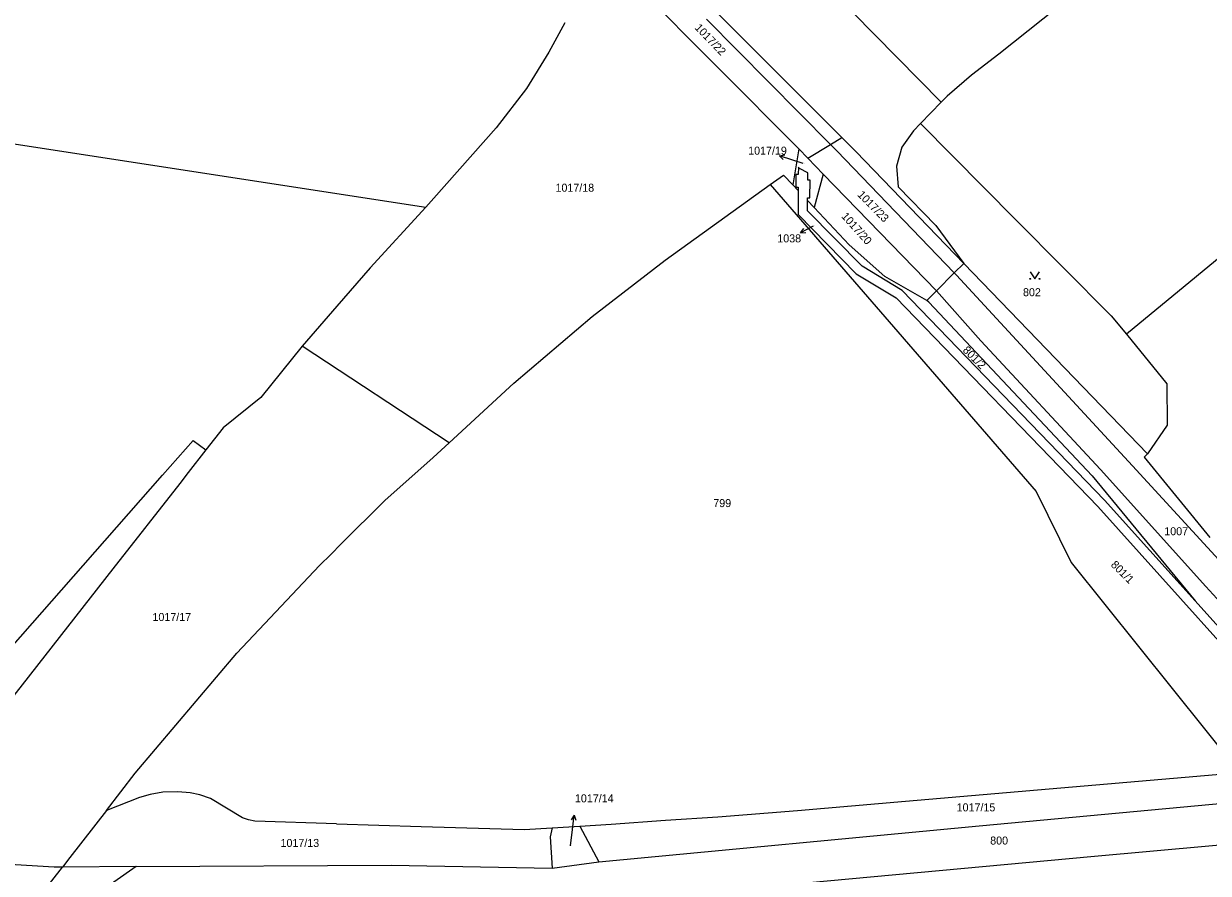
# Model space of a CAD drawing. Extents: x -738131 to -734179, y -1033447 to -1030078.
# Drawn here: x -736626.5 to -736374.8, y -1031869.7 to -1031689.1 of the extents above; entities that cross this region are included whole.
import ezdxf

# ---------------------------------------------------------------- set-up
doc = ezdxf.new("R2010")
doc.units = 0
for name, color, linetype in [('Vrstva 1', 7, 'Continuous'), ('Vrstva 2', 7, 'Continuous'), ('Vrstva 3', 7, 'Continuous'), ('Vrstva 4', 7, 'Continuous'), ('Vrstva 7', 7, 'Continuous')]:
    doc.layers.add(name, color=color, linetype=linetype)

msp = doc.modelspace()

# ---------------------------------------------------------------- linework, layer by layer
at = {"layer": 'Vrstva 1'}
for points in [[(-736431.56, -1031705.78), (-736478.56, -1031658.03)], [(-736496.26, -1031681.05), (-736461.83, -1031715.71)], [(-736403.74, -1031683.08), (-736419.34, -1031695.6)], [(-736452.7, -1031713.28), (-736480.2, -1031685.76)], [(-736511.58, -1031688.94), (-736514.98, -1031695.17)], [(-736514.98, -1031695.17), (-736519.67, -1031702.88)], [(-736419.34, -1031695.6), (-736425.13, -1031700.05)], [(-736317.82, -1031693.78), (-736392.24, -1031755.11)], [(-736736.47, -1031698.03), (-736541.12, -1031728.09)], [(-736425.13, -1031700.05), (-736430.29, -1031704.47)], [(-736519.67, -1031702.88), (-736526.15, -1031711.23)], [(-736430.29, -1031704.47), (-736431.56, -1031705.78)], [(-736431.56, -1031705.78), (-736435.97, -1031710.31)], [(-736435.97, -1031710.31), (-736437.48, -1031711.86)], [(-736435.97, -1031710.31), (-736415.73, -1031730.77)], [(-736526.15, -1031711.23), (-736539.38, -1031726.19)], [(-736437.48, -1031711.86), (-736439.92, -1031715.32)], [(-736461.83, -1031715.71), (-736463.09, -1031723.35)], [(-736459.92, -1031717.68), (-736461.83, -1031715.71)], [(-736459.92, -1031717.68), (-736455.11, -1031714.75)], [(-736455.11, -1031714.75), (-736452.7, -1031713.28)], [(-736449.65, -1031716.33), (-736452.7, -1031713.28)], [(-736439.92, -1031715.32), (-736441.07, -1031719.39)], [(-736456.65, -1031721.07), (-736459.92, -1031717.68)], [(-736426.79, -1031740.06), (-736449.65, -1031716.33)], [(-736461.92, -1031719.59), (-736461.94, -1031721.11)], [(-736461.68, -1031719.84), (-736461.92, -1031719.59)], [(-736459.93, -1031720.79), (-736461.68, -1031719.84)], [(-736459.95, -1031722.36), (-736459.93, -1031720.79)], [(-736441.07, -1031719.39), (-736440.71, -1031723.79)], [(-736490.24, -1031739.37), (-736467.89, -1031723.29)], [(-736467.89, -1031723.29), (-736465.07, -1031721.26)], [(-736467.89, -1031723.29), (-736411.42, -1031788.53)], [(-736463.09, -1031723.35), (-736465.07, -1031721.26)], [(-736462.44, -1031721.11), (-736462.46, -1031723.8)], [(-736461.94, -1031721.11), (-736462.44, -1031721.11)], [(-736459.45, -1031722.36), (-736459.95, -1031722.36)], [(-736459.48, -1031726.13), (-736459.45, -1031722.36)], [(-736456.65, -1031721.07), (-736458.59, -1031728.13)], [(-736432.58, -1031745.87), (-736456.65, -1031721.07)], [(-736461.96, -1031724.55), (-736463.09, -1031723.35)], [(-736462.46, -1031723.8), (-736461.96, -1031723.81)], [(-736461.96, -1031724.55), (-736462, -1031729.68)], [(-736461.96, -1031723.81), (-736461.96, -1031724.55)], [(-736440.71, -1031723.79), (-736432.72, -1031732.01)], [(-736541.12, -1031728.09), (-736552.89, -1031740.95)], [(-736539.38, -1031726.19), (-736541.12, -1031728.09)], [(-736460, -1031728.87), (-736459.98, -1031726.65)], [(-736459.98, -1031726.65), (-736459.98, -1031726.12)], [(-736459.98, -1031726.12), (-736459.48, -1031726.13)], [(-736458.59, -1031728.13), (-736459.98, -1031726.65)], [(-736451.11, -1031736.06), (-736458.59, -1031728.13)], [(-736462, -1031729.68), (-736449.65, -1031742.22)], [(-736448.4, -1031740.64), (-736460, -1031728.87)], [(-736415.73, -1031730.77), (-736395.45, -1031751.19)], [(-736432.72, -1031732.01), (-736426.79, -1031740.06)], [(-736443.59, -1031742.79), (-736451.11, -1031736.06)], [(-736552.89, -1031740.95), (-736560.01, -1031749.1)], [(-736505.76, -1031751.34), (-736490.24, -1031739.37)], [(-736439.91, -1031745.77), (-736448.4, -1031740.64)], [(-736428.8, -1031742.07), (-736426.79, -1031740.06)], [(-736426.79, -1031740.06), (-736387.78, -1031780.54)], [(-736449.65, -1031742.22), (-736441.16, -1031747.35)], [(-736434.66, -1031747.91), (-736443.59, -1031742.79)], [(-736432.58, -1031745.87), (-736428.8, -1031742.07)], [(-736396.85, -1031790.37), (-736439.91, -1031745.77)], [(-736432.58, -1031745.87), (-736434.66, -1031747.91)], [(-736441.16, -1031747.35), (-736398.32, -1031791.71)], [(-736434.2, -1031748.27), (-736434.66, -1031747.91)], [(-736399.5, -1031785.22), (-736434.2, -1031748.27)], [(-736560.01, -1031749.1), (-736567.35, -1031757.66)], [(-736522.38, -1031765.51), (-736505.76, -1031751.34)], [(-736395.45, -1031751.19), (-736392.24, -1031755.11)], [(-736392.24, -1031755.11), (-736383.64, -1031765.6)], [(-736567.35, -1031757.66), (-736576.16, -1031768.52)], [(-736536.1, -1031778.14), (-736567.35, -1031757.66)], [(-736536.1, -1031778.14), (-736522.38, -1031765.51)], [(-736383.64, -1031765.6), (-736383.56, -1031774.39)], [(-736576.16, -1031768.52), (-736584.15, -1031775.01)], [(-736584.15, -1031775.01), (-736587.82, -1031779.69)], [(-736383.56, -1031774.39), (-736387.78, -1031780.54)], [(-736597.05, -1031785.07), (-736590.56, -1031777.69)], [(-736590.56, -1031777.69), (-736587.82, -1031779.69)], [(-736536.1, -1031778.14), (-736539.53, -1031781.3)], [(-736587.82, -1031779.69), (-736591.56, -1031784.47)], [(-736388.45, -1031781.21), (-736387.78, -1031780.54)], [(-736388.45, -1031781.21), (-736374.52, -1031798.29)], [(-736539.53, -1031781.3), (-736549.79, -1031790.4)], [(-736613.89, -1031804.22), (-736597.05, -1031785.07)], [(-736591.56, -1031784.47), (-736593.37, -1031786.79)], [(-736399.5, -1031785.22), (-736377.64, -1031811.73)], [(-736593.37, -1031786.79), (-736607.57, -1031804.92)], [(-736411.42, -1031788.53), (-736403.94, -1031803.64)], [(-736549.79, -1031790.4), (-736559.12, -1031799.71)], [(-736377.64, -1031811.73), (-736396.85, -1031790.37)], [(-736398.32, -1031791.71), (-736355, -1031839.89)], [(-736559.12, -1031799.71), (-736561.22, -1031801.8)], [(-736561.22, -1031801.8), (-736563.69, -1031804.27)], [(-736403.94, -1031803.64), (-736368.19, -1031848.25)], [(-736607.57, -1031804.92), (-736654.08, -1031864.32)], [(-736629.29, -1031821.73), (-736613.89, -1031804.22)], [(-736563.69, -1031804.27), (-736574.17, -1031815.37)], [(-736353.52, -1031838.55), (-736377.64, -1031811.73)], [(-736581.28, -1031822.91), (-736574.17, -1031815.37)], [(-736602.83, -1031848.37), (-736581.28, -1031822.91)], [(-736608.96, -1031856.3), (-736602.83, -1031848.37)], [(-736439.15, -1031854.34), (-736368.19, -1031848.25)], [(-736601.9, -1031853.52), (-736608.96, -1031856.3)], [(-736599.7, -1031852.9), (-736601.9, -1031853.52)], [(-736597.01, -1031852.41), (-736599.7, -1031852.9)], [(-736593.81, -1031852.34), (-736597.01, -1031852.41)], [(-736591.14, -1031852.56), (-736593.81, -1031852.34)], [(-736589.14, -1031853), (-736591.14, -1031852.56)], [(-736586.85, -1031853.74), (-736589.14, -1031853)], [(-736580.02, -1031857.85), (-736586.85, -1031853.74)], [(-736423.5, -1031859.55), (-736344.17, -1031852.23)], [(-736608.96, -1031856.3), (-736616.71, -1031866.3)], [(-736479.02, -1031857.66), (-736462.09, -1031856.3)], [(-736462.09, -1031856.3), (-736439.15, -1031854.34)], [(-736578.75, -1031858.3), (-736580.02, -1031857.85)], [(-736577.43, -1031858.56), (-736578.75, -1031858.3)], [(-736560.06, -1031859.13), (-736577.43, -1031858.56)], [(-736560.06, -1031859.13), (-736542.11, -1031859.68)], [(-736508.39, -1031859.63), (-736501.69, -1031859.2)], [(-736501.69, -1031859.2), (-736490.13, -1031858.4)], [(-736490.13, -1031858.4), (-736479.02, -1031857.66)], [(-736542.11, -1031859.68), (-736520.17, -1031860.37)], [(-736520.17, -1031860.37), (-736514.22, -1031859.99)], [(-736514.22, -1031859.99), (-736514.64, -1031861.89)], [(-736514.22, -1031859.99), (-736508.39, -1031859.63)], [(-736508.39, -1031859.63), (-736504.32, -1031867.24)], [(-736504.32, -1031867.24), (-736423.5, -1031859.55)], [(-736398.99, -1031866.05), (-736337.08, -1031860.44)], [(-736514.64, -1031861.89), (-736514.22, -1031868.55)], [(-736616.71, -1031866.3), (-736618.31, -1031868.33)], [(-736474.26, -1031872.99), (-736398.99, -1031866.05)], [(-736620.05, -1031868.34), (-736643.56, -1031866.94)], [(-736623.35, -1031874.81), (-736618.31, -1031868.33)], [(-736618.31, -1031868.33), (-736620.05, -1031868.34)], [(-736602.63, -1031868.24), (-736618.31, -1031868.33)], [(-736602.63, -1031868.24), (-736612.12, -1031874.86)], [(-736602.63, -1031868.24), (-736548.43, -1031867.92)], [(-736548.43, -1031867.92), (-736514.22, -1031868.55)], [(-736514.22, -1031868.55), (-736504.32, -1031867.24)]]:
    msp.add_lwpolyline(points, dxfattribs=at)
at = {"layer": 'Vrstva 3'}
msp.add_lwpolyline([(-736412.67, -1031741.82), (-736411.67, -1031743.32), (-736410.67, -1031741.82)], dxfattribs=at)
for centre in [(-736412.67, -1031743.32), (-736410.67, -1031743.32)]:
    msp.add_circle(centre, 0.1, dxfattribs=at)
at = {"layer": 'Vrstva 4'}
for points in [[(-736481.44, -1031688.11), (-736455.11, -1031714.75)], [(-736455.11, -1031714.75), (-736453.78, -1031716.09)], [(-736453.78, -1031716.09), (-736428.8, -1031742.07)], [(-736428.8, -1031742.07), (-736428.33, -1031742.56)], [(-736428.33, -1031742.56), (-736390.93, -1031783.08)], [(-736423.14, -1031756.53), (-736432.58, -1031745.87)], [(-736397.76, -1031783.82), (-736423.14, -1031756.53)], [(-736390.93, -1031783.08), (-736340.73, -1031837.73)], [(-736375.37, -1031808.71), (-736397.76, -1031783.82)], [(-736356.68, -1031829.13), (-736375.37, -1031808.71)]]:
    msp.add_lwpolyline(points, dxfattribs=at)
at = {"layer": 'Vrstva 7'}
for p, q in [((-736465.95, -1031717.16), (-736464.84, -1031716.99)), ((-736463.09, -1031718.08), (-736465.95, -1031717.16)), ((-736465.95, -1031717.16), (-736465.15, -1031717.94)), ((-736458.8, -1031732.12), (-736461.45, -1031733.52)), ((-736461.45, -1031733.52), (-736460.8, -1031732.61)), ((-736461.45, -1031733.52), (-736460.34, -1031733.5)), ((-736509.6, -1031857.34), (-736510.21, -1031858.28)), ((-736509.95, -1031860.32), (-736509.6, -1031857.34)), ((-736509.6, -1031857.34), (-736509.22, -1031858.39))]:
    msp.add_line(p, q, dxfattribs=at)
for points in [[(-736460.89, -1031718.79), (-736463.09, -1031718.08)], [(-736510.35, -1031863.79), (-736509.95, -1031860.32)]]:
    msp.add_lwpolyline(points, dxfattribs=at)

# ---------------------------------------------------------------- texts
at = {"layer": 'Vrstva 2'}
for s, rotation, p in [('1017/22', 313.8769, (-736484.07, -1031690.07)), ('1017/23', 314.3926, (-736449.5, -1031725.56)), ('1017/20', 311.8715, (-736452.91, -1031730.1)), ('801/2', 315, (-736427.14, -1031758.62)), ('801/1', 315, (-736395.66, -1031804.23))]:
    msp.add_text(s, height=1.7, rotation=rotation, dxfattribs=at).set_placement(p)
for s, height, p in [('1017/19', 0.1, (-736461.11, -1031718.79)), ('1017/18', 1.7, (-736513.54, -1031724.8)), ('1038', 0.1, (-736458.8, -1031732.12)), ('802', 1.7, (-736414.2, -1031747.01)), ('799', 1.7, (-736480.01, -1031791.83)), ('1007', 1.7, (-736384.18, -1031797.81)), ('1017/17', 1.7, (-736599.18, -1031816.04)), ('1017/15', 1.7, (-736428.3, -1031856.5)), ('1017/13', 1.7, (-736571.97, -1031864.06)), ('1017/14', 0.1, (-736510.35, -1031863.79)), ('800', 1.7, (-736421.17, -1031863.55))]:
    msp.add_text(s, height=height, dxfattribs=at).set_placement(p)
at = {"layer": 'Vrstva 7'}
for s, p in [('1017/19', (-736472.6, -1031716.93)), ('1038', (-736466.41, -1031735.57)), ('1017/14', (-736509.41, -1031854.58))]:
    msp.add_text(s, height=1.7, dxfattribs=at).set_placement(p)

doc.saveas('drawing.dxf')
